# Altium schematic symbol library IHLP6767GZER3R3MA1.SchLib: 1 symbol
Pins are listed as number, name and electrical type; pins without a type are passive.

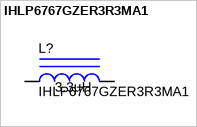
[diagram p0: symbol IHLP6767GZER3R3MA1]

## IHLP6767GZER3R3MA1
designator L?  ValueDisplayed: 3.3µH
INDUCTOR POWER 3.3UH 54A SMD; Manufacturer: Vishay-Dale; Alternate Manufacturer: Any; Alternate PartNumber: Equivalent; Ind_H: 1.0E-6; Imax_A: 41; Irms: 32A @ 40C rise; Isat: 49A @ 20% inductance drop; Value1: 0.0018 ohm; Material: Powdered Iron; Expr1028: Digi-Key; U/M: EA
signal-integrity model Inductor
simulation model Inductor
footprint IHLP6767GZ (IHLP6767GZ VISHAY DALE INDUCTOR)
pins: 1, 2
